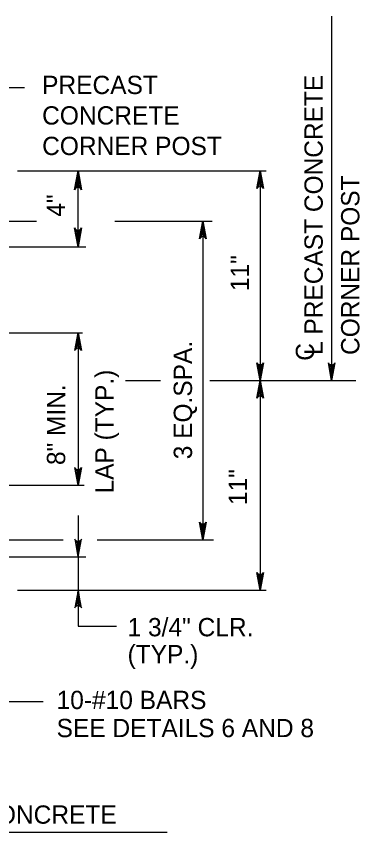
# Model space of a CAD drawing. Extents: x 3351 to 8430, y -3586 to 1457.
# Drawn here: x 5233.4 to 5291, y 167.6 to 304.6 of the extents above; entities that cross this region are included whole.
import ezdxf

# ---------------------------------------------------------------- set-up
doc = ezdxf.new("R2010")
doc.units = 0
doc.layers.add('1', color=7, linetype='Continuous')

msp = doc.modelspace()

# ---------------------------------------------------------------- linework, layer by layer
at = {"layer": '1'}
for p, q in [((5286.27, 304.64), (5286.27, 243.52)), ((5226.77, 292.7), (5234.76, 292.7)), ((5233.59, 278.72), (5275.3, 278.72)), ((5243.76, 265.92), (5243.76, 278.72)), ((5274.28, 278.72), (5274.28, 243.52)), ((5228.35, 270.27), (5236.82, 270.27)), ((5249.95, 270.27), (5266.22, 270.27)), ((5264.68, 270.27), (5264.68, 216.77)), ((5212.4, 265.92), (5245.08, 265.92)), ((5228.63, 251.51), (5244.51, 251.51)), ((5243.76, 251.51), (5243.76, 225.92)), ((5251.74, 243.52), (5257.58, 243.52)), ((5265.85, 243.52), (5290.33, 243.52)), ((5274.28, 243.52), (5274.28, 208.32)), ((5228.63, 225.92), (5244.81, 225.92)), ((5243.76, 220.83), (5243.76, 213.91)), ((5228.35, 216.77), (5241.27, 216.77)), ((5246.99, 216.77), (5266.45, 216.77)), ((5227.89, 213.91), (5245.08, 213.91)), ((5243.76, 213.91), (5243.76, 208.32)), ((5233.59, 208.32), (5275.3, 208.32)), ((5243.76, 208.32), (5243.76, 202.26)), ((5243.76, 202.26), (5250.23, 202.26)), ((5224.09, 189.64), (5237.91, 189.64)), ((5258.68, 167.61), (5197.41, 167.61))]:
    msp.add_line(p, q, dxfattribs=at)
for points in [[(5243.76, 278.72), (5244.36, 275.54), (5244.19, 275.79), (5243.97, 275.91), (5243.76, 275.95), (5243.55, 275.91), (5243.33, 275.79), (5243.16, 275.54), (5243.76, 278.72), (5243.33, 275.79), (5243.55, 275.91), (5243.76, 278.72), (5243.76, 275.95), (5243.97, 275.91), (5243.76, 278.72), (5244.19, 275.79)], [(5274.28, 278.72), (5274.84, 275.74), (5274.68, 275.97), (5274.48, 276.09), (5274.28, 276.12), (5274.08, 276.09), (5273.88, 275.97), (5273.72, 275.74), (5274.28, 278.72), (5273.88, 275.97), (5274.08, 276.09), (5274.28, 278.72), (5274.28, 276.12), (5274.48, 276.09), (5274.28, 278.72), (5274.68, 275.97)], [(5264.68, 270.27), (5265.24, 267.29), (5265.08, 267.52), (5264.88, 267.64), (5264.68, 267.67), (5264.48, 267.64), (5264.28, 267.52), (5264.12, 267.29), (5264.68, 270.27), (5264.28, 267.52), (5264.48, 267.64), (5264.68, 270.27), (5264.68, 267.67), (5264.88, 267.64), (5264.68, 270.27), (5265.08, 267.52)], [(5243.76, 265.92), (5243.16, 269.11), (5243.33, 268.86), (5243.55, 268.73), (5243.76, 268.7), (5243.97, 268.73), (5244.19, 268.86), (5244.36, 269.11), (5243.76, 265.92), (5244.19, 268.86), (5243.97, 268.73), (5243.76, 265.92), (5243.76, 268.7), (5243.55, 268.73), (5243.76, 265.92), (5243.33, 268.86)], [(5243.76, 251.51), (5244.32, 248.53), (5244.16, 248.76), (5243.96, 248.88), (5243.76, 248.91), (5243.56, 248.88), (5243.36, 248.76), (5243.2, 248.53), (5243.76, 251.51), (5243.36, 248.76), (5243.56, 248.88), (5243.76, 251.51), (5243.76, 248.91), (5243.96, 248.88), (5243.76, 251.51), (5244.16, 248.76)], [(5274.28, 243.52), (5273.72, 246.5), (5273.88, 246.27), (5274.08, 246.16), (5274.28, 246.12), (5274.48, 246.16), (5274.68, 246.27), (5274.84, 246.5), (5274.28, 243.52), (5274.68, 246.27), (5274.48, 246.16), (5274.28, 243.52), (5274.28, 246.12), (5274.08, 246.16), (5274.28, 243.52), (5273.88, 246.27)], [(5286.27, 243.52), (5285.72, 246.5), (5285.87, 246.27), (5286.07, 246.16), (5286.27, 246.12), (5286.47, 246.16), (5286.67, 246.27), (5286.83, 246.5), (5286.27, 243.52), (5286.67, 246.27), (5286.47, 246.16), (5286.27, 243.52), (5286.27, 246.12), (5286.07, 246.16), (5286.27, 243.52), (5285.87, 246.27)], [(5274.28, 243.52), (5274.84, 240.54), (5274.68, 240.77), (5274.48, 240.89), (5274.28, 240.92), (5274.08, 240.89), (5273.88, 240.77), (5273.72, 240.54), (5274.28, 243.52), (5273.88, 240.77), (5274.08, 240.89), (5274.28, 243.52), (5274.28, 240.92), (5274.48, 240.89), (5274.28, 243.52), (5274.68, 240.77)], [(5274.28, 243.52), (5274.84, 240.54), (5274.68, 240.77), (5274.48, 240.89), (5274.28, 240.92), (5274.08, 240.89), (5273.88, 240.77), (5273.72, 240.54), (5274.28, 243.52), (5273.88, 240.77), (5274.08, 240.89), (5274.28, 243.52), (5274.28, 240.92), (5274.48, 240.89), (5274.28, 243.52), (5274.68, 240.77)], [(5243.76, 225.92), (5243.2, 228.9), (5243.36, 228.67), (5243.56, 228.55), (5243.76, 228.52), (5243.96, 228.55), (5244.16, 228.67), (5244.32, 228.9), (5243.76, 225.92), (5244.16, 228.67), (5243.96, 228.55), (5243.76, 225.92), (5243.76, 228.52), (5243.56, 228.55), (5243.76, 225.92), (5243.36, 228.67)], [(5264.68, 216.77), (5264.12, 219.75), (5264.28, 219.52), (5264.48, 219.4), (5264.68, 219.37), (5264.88, 219.4), (5265.08, 219.52), (5265.24, 219.75), (5264.68, 216.77), (5265.08, 219.52), (5264.88, 219.4), (5264.68, 216.77), (5264.68, 219.37), (5264.48, 219.4), (5264.68, 216.77), (5264.28, 219.52)], [(5243.76, 213.91), (5244.32, 216.89), (5244.16, 216.66), (5243.96, 216.55), (5243.76, 216.51), (5243.56, 216.55), (5243.36, 216.66), (5243.2, 216.89), (5243.76, 213.91), (5243.36, 216.66), (5243.56, 216.55), (5243.76, 213.91), (5243.76, 216.51), (5243.96, 216.55), (5243.76, 213.91), (5244.16, 216.66)], [(5274.28, 208.32), (5273.72, 211.3), (5273.88, 211.07), (5274.08, 210.95), (5274.28, 210.92), (5274.48, 210.95), (5274.68, 211.07), (5274.84, 211.3), (5274.28, 208.32), (5274.68, 211.07), (5274.48, 210.95), (5274.28, 208.32), (5274.28, 210.92), (5274.08, 210.95), (5274.28, 208.32), (5273.88, 211.07)], [(5243.76, 208.32), (5243.2, 205.34), (5243.36, 205.57), (5243.56, 205.68), (5243.76, 205.72), (5243.96, 205.68), (5244.16, 205.57), (5244.32, 205.34), (5243.76, 208.32), (5244.16, 205.57), (5243.96, 205.68), (5243.76, 208.32), (5243.76, 205.72), (5243.56, 205.68), (5243.76, 208.32), (5243.36, 205.57)]]:
    msp.add_lwpolyline(points, dxfattribs=at)

# ---------------------------------------------------------------- texts
for s, height, p in [('PRECAST', 3.072, (5237.74, 291.59)), ('CONCRETE', 3.072, (5237.74, 286.47)), ('CORNER POST', 3.0721, (5237.74, 281.35)), ('1 3/4" CLR.', 3.0721, (5252.06, 200.57)), ('(TYP.)', 3.072, (5252.06, 196.03)), ('10-#10 BARS', 3.0721, (5240.16, 188.35)), ('SEE DETAILS 6 AND 8', 3.0721, (5240.16, 183.64)), ('L PRECAST CONCRETE', 3.0721, (5203.22, 169.11))]:
    msp.add_text(s, height=height, dxfattribs=at).set_placement(p)
for s, height, p in [('L PRECAST CONCRETE', 3.0721, (5284.78, 247.8)), ('CORNER POST', 3.0721, (5290.92, 247.8)), ('4"', 3.072, (5241.59, 271)), ('11"', 3.072, (5272.41, 258.51)), ('3 EQ.SPA.', 3.072, (5262.87, 230.29)), ('C', 3.07, (5283.33, 246.82)), ('LAP (TYP.)', 3.072, (5249.71, 224.55)), ('8" MIN.', 3.072, (5241.61, 229.32)), ('11"', 3.072, (5272.08, 222.6))]:
    msp.add_text(s, height=height, rotation=90, dxfattribs=at).set_placement(p)

doc.saveas('drawing.dxf')
